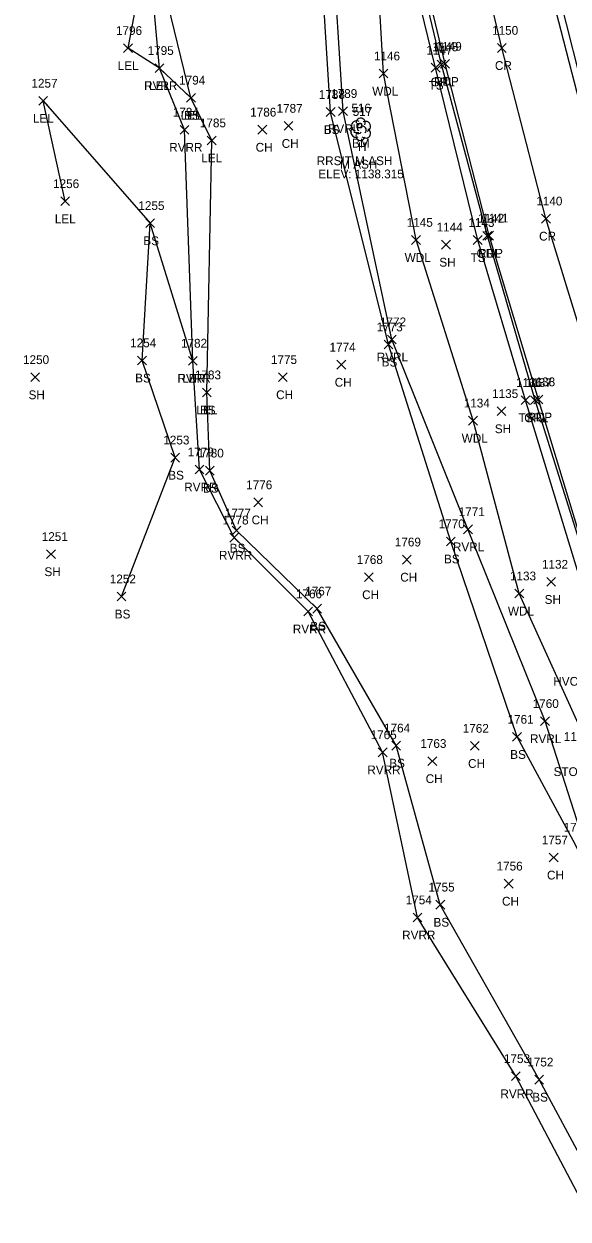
# Model space of a CAD drawing. Extents: x 1545627 to 1546562, y 571176 to 576667.
# Drawn here: x 1546048.6 to 1546172.5, y 571704.9 to 571977 of the extents above; entities that cross this region are included whole.
import ezdxf

# ---------------------------------------------------------------- set-up
doc = ezdxf.new("R2010")
doc.units = 0
for name, color, linetype in [('C_A', 7, 'Continuous'), ('C_C', 7, 'Continuous'), ('C_I', 7, 'Continuous'), ('CPBM', 7, 'Continuous'), ('L_A', 7, 'Continuous'), ('L_C', 7, 'Continuous'), ('L_I', 7, 'Continuous'), ('L_TIC', 7, 'Continuous'), ('LARO', 7, 'Continuous'), ('LAWA', 7, 'Continuous'), ('LAWE', 7, 'Continuous'), ('LELB', 7, 'Continuous'), ('LTD', 7, 'Continuous'), ('P_A', 7, 'Continuous'), ('P_I', 7, 'Continuous'), ('P_TIC', 7, 'Continuous'), ('PET', 7, 'Continuous'), ('PRC', 7, 'Continuous'), ('PSU', 7, 'Continuous'), ('R_A', 7, 'Continuous'), ('R_I', 7, 'Continuous'), ('R_TIC', 7, 'Continuous'), ('RGR', 7, 'Continuous')]:
    doc.layers.add(name, color=color, linetype=linetype)

msp = doc.modelspace()

# ---------------------------------------------------------------- linework, layer by layer
at = {"layer": 'CPBM'}
for p, q in [((1546124.51, 571953.36), (1546124.51, 571954.36)), ((1546124.51, 571954.36), (1546125.51, 571954.36)), ((1546125.51, 571953.36), (1546124.51, 571953.36)), ((1546125.01, 571953.86), (1546125.01, 571953.86)), ((1546125.01, 571953.86), (1546125.01, 571953.86)), ((1546125.51, 571954.36), (1546125.51, 571953.36))]:
    msp.add_line(p, q, dxfattribs=at)
at = {"layer": 'L_TIC'}
for points in [[(1546071.29, 571970.5), (1546073.29, 571972.5)], [(1546073.29, 571970.5), (1546071.29, 571972.5)], [(1546078.44, 571965.95), (1546080.44, 571967.95)], [(1546080.44, 571965.95), (1546078.44, 571967.95)], [(1546078.44, 571965.95), (1546080.44, 571967.95)], [(1546080.44, 571965.95), (1546078.44, 571967.95)], [(1546129.49, 571964.71), (1546131.49, 571966.71)], [(1546131.49, 571964.71), (1546129.49, 571966.71)], [(1546141.36, 571966.05), (1546143.36, 571968.05)], [(1546143.36, 571966.05), (1546141.36, 571968.05)], [(1546085.62, 571959.2), (1546087.62, 571961.2)], [(1546087.62, 571959.2), (1546085.62, 571961.2)], [(1546085.62, 571959.2), (1546087.62, 571961.2)], [(1546087.62, 571959.2), (1546085.62, 571961.2)], [(1546051.97, 571958.51), (1546053.97, 571960.51)], [(1546053.97, 571958.51), (1546051.97, 571960.51)], [(1546117.44, 571955.95), (1546119.44, 571957.95)], [(1546119.44, 571955.95), (1546117.44, 571957.95)], [(1546120.26, 571956.17), (1546122.26, 571958.17)], [(1546122.26, 571956.17), (1546120.26, 571958.17)], [(1546084.16, 571951.92), (1546086.16, 571953.92)], [(1546086.16, 571951.92), (1546084.16, 571953.92)], [(1546101.87, 571951.93), (1546103.87, 571953.93)], [(1546103.87, 571951.93), (1546101.87, 571953.93)], [(1546107.82, 571952.8), (1546109.82, 571954.8)], [(1546109.82, 571952.8), (1546107.82, 571954.8)], [(1546090.35, 571949.48), (1546092.35, 571951.48)], [(1546092.35, 571949.48), (1546090.35, 571951.48)], [(1546056.96, 571935.64), (1546058.96, 571937.64)], [(1546058.96, 571935.64), (1546056.96, 571937.64)], [(1546076.34, 571930.65), (1546078.34, 571932.65)], [(1546078.34, 571930.65), (1546076.34, 571932.65)], [(1546136.89, 571926.83), (1546138.89, 571928.83)], [(1546138.89, 571926.83), (1546136.89, 571928.83)], [(1546150.94, 571926.81), (1546152.94, 571928.81)], [(1546152.94, 571926.81), (1546150.94, 571928.81)], [(1546143.72, 571925.76), (1546145.72, 571927.76)], [(1546145.72, 571925.76), (1546143.72, 571927.76)], [(1546130.62, 571903.03), (1546132.62, 571905.03)], [(1546132.62, 571903.03), (1546130.62, 571905.03)], [(1546131.38, 571904.18), (1546133.38, 571906.18)], [(1546133.38, 571904.18), (1546131.38, 571906.18)], [(1546074.47, 571899.4), (1546076.47, 571901.4)], [(1546076.47, 571899.4), (1546074.47, 571901.4)], [(1546086.04, 571899.32), (1546088.04, 571901.32)], [(1546088.04, 571899.32), (1546086.04, 571901.32)], [(1546086.04, 571899.32), (1546088.04, 571901.32)], [(1546088.04, 571899.32), (1546086.04, 571901.32)], [(1546119.88, 571898.43), (1546121.88, 571900.43)], [(1546121.88, 571898.43), (1546119.88, 571900.43)], [(1546050.14, 571895.58), (1546052.14, 571897.58)], [(1546052.14, 571895.58), (1546050.14, 571897.58)], [(1546106.53, 571895.59), (1546108.53, 571897.59)], [(1546108.53, 571895.59), (1546106.53, 571897.59)], [(1546089.22, 571892.11), (1546091.22, 571894.11)], [(1546091.22, 571892.11), (1546089.22, 571894.11)], [(1546089.22, 571892.11), (1546091.22, 571894.11)], [(1546091.22, 571892.11), (1546089.22, 571894.11)], [(1546161.84, 571890.38), (1546163.84, 571892.38)], [(1546163.84, 571890.38), (1546161.84, 571892.38)], [(1546149.88, 571885.7), (1546151.88, 571887.7)], [(1546151.88, 571885.7), (1546149.88, 571887.7)], [(1546156.35, 571887.85), (1546158.35, 571889.85)], [(1546158.35, 571887.85), (1546156.35, 571889.85)], [(1546082.01, 571877.28), (1546084.01, 571879.28)], [(1546084.01, 571877.28), (1546082.01, 571879.28)], [(1546087.58, 571874.57), (1546089.58, 571876.57)], [(1546089.58, 571874.57), (1546087.58, 571876.57)], [(1546089.93, 571874.32), (1546091.93, 571876.32)], [(1546091.93, 571874.32), (1546089.93, 571876.32)], [(1546100.95, 571867.09), (1546102.95, 571869.09)], [(1546102.95, 571867.09), (1546100.95, 571869.09)], [(1546095.49, 571859.06), (1546097.49, 571861.06)], [(1546097.49, 571859.06), (1546095.49, 571861.06)], [(1546096.02, 571860.67), (1546098.02, 571862.67)], [(1546098.02, 571860.67), (1546096.02, 571862.67)], [(1546148.73, 571860.96), (1546150.73, 571862.96)], [(1546150.73, 571860.96), (1546148.73, 571862.96)], [(1546144.83, 571858.21), (1546146.83, 571860.21)], [(1546146.83, 571858.21), (1546144.83, 571860.21)], [(1546053.75, 571855.31), (1546055.75, 571857.31)], [(1546055.75, 571855.31), (1546053.75, 571857.31)], [(1546134.81, 571854.06), (1546136.81, 571856.06)], [(1546136.81, 571854.06), (1546134.81, 571856.06)], [(1546126.13, 571850.07), (1546128.13, 571852.07)], [(1546128.13, 571850.07), (1546126.13, 571852.07)], [(1546167.7, 571848.99), (1546169.7, 571850.99)], [(1546169.7, 571848.99), (1546167.7, 571850.99)], [(1546069.82, 571845.66), (1546071.82, 571847.66)], [(1546071.82, 571845.66), (1546069.82, 571847.66)], [(1546160.42, 571846.33), (1546162.42, 571848.33)], [(1546162.42, 571846.33), (1546160.42, 571848.33)], [(1546112.32, 571842.26), (1546114.32, 571844.26)], [(1546114.32, 571842.26), (1546112.32, 571844.26)], [(1546114.39, 571842.89), (1546116.39, 571844.89)], [(1546116.39, 571842.89), (1546114.39, 571844.89)], [(1546166.29, 571817.28), (1546168.29, 571819.28)], [(1546168.29, 571817.28), (1546166.29, 571819.28)], [(1546159.91, 571813.7), (1546161.91, 571815.7)], [(1546161.91, 571813.7), (1546159.91, 571815.7)], [(1546129.29, 571810.19), (1546131.29, 571812.19)], [(1546131.29, 571810.19), (1546129.29, 571812.19)], [(1546132.35, 571811.72), (1546134.35, 571813.72)], [(1546134.35, 571811.72), (1546132.35, 571813.72)], [(1546150.27, 571811.65), (1546152.27, 571813.65)], [(1546152.27, 571811.65), (1546150.27, 571813.65)], [(1546140.61, 571808.19), (1546142.61, 571810.19)], [(1546142.61, 571808.19), (1546140.61, 571810.19)], [(1546168.24, 571786.24), (1546170.24, 571788.24)], [(1546170.24, 571786.24), (1546168.24, 571788.24)], [(1546157.99, 571780.29), (1546159.99, 571782.29)], [(1546159.99, 571780.29), (1546157.99, 571782.29)], [(1546142.43, 571775.5), (1546144.43, 571777.5)], [(1546144.43, 571775.5), (1546142.43, 571777.5)], [(1546137.23, 571772.59), (1546139.23, 571774.59)], [(1546139.23, 571772.59), (1546137.23, 571774.59)], [(1546159.61, 571736.45), (1546161.61, 571738.45)], [(1546161.61, 571736.45), (1546159.61, 571738.45)], [(1546164.93, 571735.68), (1546166.93, 571737.68)], [(1546166.93, 571735.68), (1546164.93, 571737.68)]]:
    msp.add_lwpolyline(points, dxfattribs=at)
at = {"layer": 'LARO'}
for points in [[(1546090.22, 571893.11), (1546091.35, 571950.48), (1546086.62, 571960.2), (1546079.44, 571966.95), (1546072.29, 571971.5), (1546074.85, 571984.99), (1546068.68, 572037.28), (1546072.51, 572073.37), (1546063.14, 572085.78)], [(1546057.96, 571936.64), (1546052.97, 571959.51)], [(1546052.97, 571959.51), (1546077.34, 571931.65)], [(1546087.04, 571900.32), (1546077.34, 571931.65)]]:
    msp.add_lwpolyline(points, dxfattribs=at)
at = {"layer": 'LAWA'}
msp.add_lwpolyline([(1546207.43, 571744.29), (1546192.22, 571778.13), (1546177.19, 571812.62), (1546161.42, 571847.33), (1546150.88, 571886.7), (1546137.89, 571927.83), (1546130.49, 571965.71), (1546128.09, 572007.86), (1546121.49, 572030.97), (1546115.77, 572071.63), (1546116.87, 572083.76)], dxfattribs=at)
at = {"layer": 'LAWE'}
for points in [[(1546291.68, 571509.09), (1546276, 571554.51), (1546265.8, 571586.47), (1546246.73, 571630.75), (1546234.82, 571659.95), (1546216.56, 571711.52), (1546198.01, 571746.58), (1546176.48, 571789.7), (1546167.29, 571818.28), (1546149.73, 571861.96), (1546132.38, 571905.18), (1546121.26, 571957.17), (1546118.8, 571996.68)], [(1546258.96, 571503.98), (1546247.25, 571543.2), (1546232.25, 571576.91), (1546212.48, 571618.99), (1546196.14, 571656.31), (1546182.65, 571695.75), (1546160.61, 571737.45), (1546138.23, 571773.59), (1546130.29, 571811.19), (1546113.32, 571843.26), (1546096.49, 571860.06), (1546088.58, 571875.57), (1546087.04, 571900.32), (1546085.16, 571952.92), (1546079.44, 571966.95), (1546077.79, 571985.49)]]:
    msp.add_lwpolyline(points, dxfattribs=at)
at = {"layer": 'LELB'}
for points in [[(1546316.39, 571519.99), (1546295.99, 571560.57), (1546277.23, 571599.95), (1546257.92, 571640.86), (1546240.42, 571680.68), (1546227.25, 571713.56), (1546212.6, 571746.96), (1546199.61, 571780.81), (1546186.37, 571815.41), (1546174.93, 571851.82), (1546162.84, 571891.38), (1546151.94, 571927.81), (1546142.36, 571967.05), (1546132.26, 572008.4), (1546126.74, 572032.68), (1546118.89, 572071.99), (1546116.87, 572083.76)], [(1546086.62, 571960.2), (1546080.58, 571984.87), (1546076.82, 572034.33), (1546074.32, 572074.31)], [(1546289.09, 571508.47), (1546272.41, 571554.88), (1546264.55, 571586.76), (1546244.35, 571627.87), (1546230.42, 571657.81), (1546213.76, 571710.05), (1546197.12, 571744.15), (1546174.21, 571790.13), (1546160.91, 571814.7), (1546145.83, 571859.21), (1546131.62, 571904.03), (1546118.44, 571956.95), (1546115.97, 571995.99), (1546108.78, 572035.92), (1546103.73, 572068.58)], [(1546070.82, 571846.66), (1546083.01, 571878.28), (1546075.47, 571900.4), (1546077.34, 571931.65)], [(1546264.48, 571501.32), (1546248.81, 571543.43), (1546237.8, 571575.68), (1546217.63, 571618.65), (1546201.94, 571655.46), (1546187.64, 571696.37), (1546165.93, 571736.68), (1546143.43, 571776.5), (1546133.35, 571812.72), (1546115.39, 571843.89), (1546097.02, 571861.67), (1546090.93, 571875.32), (1546090.22, 571893.11)]]:
    msp.add_lwpolyline(points, dxfattribs=at)
at = {"layer": 'LTD'}
msp.add_line((1546125.25, 571953.07), (1546125.25, 571953.07), dxfattribs=at)
msp.add_line((1546125.25, 571953.07), (1546125.25, 571953.07), dxfattribs=at)
msp.add_arc((1546125.3, 571954.51), 1.05, 335.5272, 180.9563, dxfattribs=at)
for centre, major_axis, ratio, start_param, end_param in [((1546124.17, 571952.36), (0.58, -1.04), 0.959034, 3.141593, 6.283185), ((1546124.46, 571953.74), (1.21, -0.51), 0.895232, 1.570796, 4.712389), ((1546125.05, 571953.53), (-0.208, -0.792), 0.645439, 3.141593, 6.283185), ((1546125.75, 571952.9), (-0.5, 0.667), 0.989748, 3.141593, 6.283185), ((1546126.25, 571952.24), (-1.09, 0.79), 0.841452, 1.570796, 4.712389), ((1546126.3, 571953.66), (-1.14, -0.48), 0.949671, 1.570796, 4.712389), ((1546125.25, 571951.57), (0.26, 1.06), 0.942809, 1.570796, 4.712389), ((1546124.8, 571952.32), (-0.625, -0.083), 0.423636, 0, 3.141593)]:
    msp.add_ellipse(centre, major_axis=major_axis, ratio=ratio, start_param=start_param, end_param=end_param, dxfattribs=at)
at = {"layer": 'P_TIC'}
for points in [[(1546156.43, 571970.54), (1546158.43, 571972.54)], [(1546158.43, 571970.54), (1546156.43, 571972.54)], [(1546143.5, 571966.92), (1546145.5, 571968.92)], [(1546145.5, 571966.92), (1546143.5, 571968.92)], [(1546166.5, 571931.69), (1546168.5, 571933.69)], [(1546168.5, 571931.69), (1546166.5, 571933.69)], [(1546153.55, 571927.81), (1546155.55, 571929.81)], [(1546155.55, 571927.81), (1546153.55, 571929.81)], [(1546164.76, 571890.53), (1546166.76, 571892.53)], [(1546166.76, 571890.53), (1546164.76, 571892.53)]]:
    msp.add_lwpolyline(points, dxfattribs=at)
at = {"layer": 'PET'}
for points in [[(1546536.21, 571181.01), (1546508.17, 571223.67), (1546475.69, 571271.66), (1546448.41, 571311.32), (1546419.18, 571354.19), (1546394.92, 571390.86), (1546367.78, 571434.2), (1546346.92, 571469.65), (1546328.81, 571502.75), (1546318.67, 571520.99), (1546297.7, 571561.78), (1546279.07, 571601.48), (1546260.13, 571643.3), (1546242.96, 571682.18), (1546229.29, 571714.28), (1546215.95, 571747.93), (1546202.6, 571782.08), (1546189.82, 571816.62), (1546177.58, 571852.76), (1546165.76, 571891.53), (1546154.55, 571928.81), (1546144.5, 571967.92), (1546134.66, 572009.13)], [(1546559.08, 571194.5), (1546529.75, 571240.45), (1546499.79, 571284.88), (1546470.8, 571327.72), (1546443.13, 571367.68), (1546417.68, 571406.9), (1546392.95, 571446.31), (1546370.2, 571483.99), (1546352.76, 571515), (1546343.41, 571532.43), (1546322.94, 571573.04), (1546306.85, 571607.13), (1546293.98, 571634.56), (1546271.4, 571685.96), (1546259.46, 571713.47), (1546245.43, 571748.53), (1546227.67, 571795.22), (1546213.04, 571834.88), (1546205.18, 571857.76), (1546192.7, 571896.53), (1546178.72, 571945.47), (1546165.66, 571996.1)]]:
    msp.add_lwpolyline(points, dxfattribs=at)
at = {"layer": 'PRC'}
msp.add_lwpolyline([(1546547.34, 571187.72), (1546518.74, 571231.86), (1546487.31, 571278.43), (1546459.33, 571318.89), (1546430.57, 571360.77), (1546405.96, 571398.26), (1546380.25, 571440.1), (1546358.53, 571476.99), (1546340.41, 571508.44), (1546330.22, 571526.95), (1546310.11, 571567.47), (1546291.29, 571606.95), (1546272.42, 571649.01), (1546255.63, 571687.66), (1546242.53, 571719.45), (1546229.29, 571753.1), (1546216.08, 571786.74), (1546203.35, 571821.01), (1546191.26, 571856.19), (1546178.74, 571896.13), (1546167.5, 571932.69), (1546157.43, 571971.54), (1546147.89, 572011.79)], dxfattribs=at)
at = {"layer": 'PSU'}
msp.add_lwpolyline([(1546344.91, 571533.75), (1546324.24, 571573.75), (1546307.57, 571607.61), (1546295.25, 571635.34), (1546272.39, 571686.56), (1546261.3, 571714.23), (1546246.81, 571749.3), (1546229.82, 571796.03), (1546214.93, 571836.38), (1546208.22, 571856.11), (1546194.62, 571896.65), (1546180.08, 571945.81), (1546167.4, 571995.97), (1546161.66, 572024.84), (1546155.58, 572044.54)], dxfattribs=at)
at = {"layer": 'R_TIC'}
for points in [[(1546142.68, 571966.8), (1546144.68, 571968.8)], [(1546144.68, 571966.8), (1546142.68, 571968.8)], [(1546153.15, 571927.78), (1546155.15, 571929.78)], [(1546155.15, 571927.78), (1546153.15, 571929.78)], [(1546164.01, 571890.35), (1546166.01, 571892.35)], [(1546166.01, 571890.35), (1546164.01, 571892.35)]]:
    msp.add_lwpolyline(points, dxfattribs=at)
at = {"layer": 'RGR'}
msp.add_lwpolyline([(1546318.09, 571520.89), (1546297.39, 571561.7), (1546278.61, 571601.26), (1546259.67, 571643.05), (1546242.43, 571682.09), (1546228.78, 571714.21), (1546215.19, 571747.99), (1546202.24, 571781.5), (1546189.29, 571816.51), (1546177.18, 571852.71), (1546165.01, 571891.35), (1546154.15, 571928.78), (1546143.68, 571967.8), (1546133.91, 572008.79), (1546128.63, 572033), (1546121.13, 572073.3), (1546118.95, 572085.97)], dxfattribs=at)

# ---------------------------------------------------------------- texts
at = {"layer": 'C_A'}
for s, p in [('BM', (1546123.33, 571948.86)), ('HVCTRL', (1546169.17, 571826.35))]:
    msp.add_text(s, height=2, dxfattribs=at).set_placement(p)
at = {"layer": 'C_C'}
for s, p in [('RRSIT M ASH', (1546115.27, 571944.86)), ('ELEV: 1138.315', (1546115.63, 571941.86))]:
    msp.add_text(s, height=2, dxfattribs=at).set_placement(p)
at = {"layer": 'C_I'}
msp.add_text('516', height=2, dxfattribs=at).set_placement((1546123.16, 571956.86))
at = {"layer": 'L_A'}
for s, p in [('LEL', (1546069.93, 571966.5)), ('RVRR', (1546075.95, 571961.95)), ('LEL', (1546077.08, 571961.95)), ('TS', (1546140.77, 571962.05)), ('WDL', (1546127.91, 571960.71)), ('LEL', (1546050.61, 571954.51)), ('LEL', (1546084.26, 571955.2)), ('BS', (1546085.06, 571955.2)), ('BS', (1546116.88, 571951.95)), ('RVRL', (1546117.83, 571952.17)), ('CH', (1546107.3, 571948.8)), ('H', (1546124.69, 571948.07)), ('RVRR', (1546081.67, 571947.92)), ('LEL', (1546088.98, 571945.48)), ('CH', (1546101.36, 571947.93)), ('LEL', (1546055.6, 571931.64)), ('BS', (1546075.78, 571926.65)), ('WDL', (1546135.31, 571922.83)), ('SH', (1546143.2, 571921.76)), ('TS', (1546150.35, 571922.81)), ('RVRL', (1546128.94, 571900.18)), ('BS', (1546130.06, 571899.03)), ('BS', (1546073.91, 571895.4)), ('RVRR', (1546083.56, 571895.32)), ('LER', (1546084.63, 571895.32)), ('CH', (1546119.37, 571894.43)), ('SH', (1546049.63, 571891.58)), ('CH', (1546106.02, 571891.59)), ('LEL', (1546087.85, 571888.11)), ('BS', (1546088.66, 571888.11)), ('TS', (1546161.25, 571886.38)), ('SH', (1546155.84, 571883.85)), ('WDL', (1546148.3, 571881.7)), ('BS', (1546081.45, 571873.28)), ('RVRR', (1546085.09, 571870.57)), ('BS', (1546089.37, 571870.32)), ('CH', (1546100.44, 571863.09)), ('BS', (1546095.46, 571856.67)), ('RVRL', (1546146.3, 571856.96)), ('RVRR', (1546093, 571855.06)), ('BS', (1546144.27, 571854.21)), ('SH', (1546053.24, 571851.31)), ('CH', (1546134.3, 571850.06)), ('CH', (1546125.62, 571846.07)), ('SH', (1546167.19, 571844.99)), ('WDL', (1546158.83, 571842.33)), ('BS', (1546069.26, 571841.66)), ('RVRR', (1546109.83, 571838.26)), ('BS', (1546113.83, 571838.89)), ('RVRL', (1546163.86, 571813.28)), ('BS', (1546159.35, 571809.7)), ('BS', (1546131.79, 571807.72)), ('CH', (1546149.75, 571807.65)), ('RVRR', (1546126.8, 571806.19)), ('CH', (1546140.09, 571804.19)), ('STONE', (1546169.23, 571805.79)), ('CH', (1546167.73, 571782.24)), ('CH', (1546157.48, 571776.29)), ('BS', (1546141.87, 571771.5)), ('RVRR', (1546134.74, 571768.59)), ('RVRR', (1546157.12, 571732.45)), ('BS', (1546164.37, 571731.68))]:
    msp.add_text(s, height=2, dxfattribs=at).set_placement(p)
at = {"layer": 'L_C'}
msp.add_text('M ASH', height=2, dxfattribs=at).set_placement((1546120.62, 571944.07))
at = {"layer": 'L_I'}
for s, p in [('1796', (1546069.54, 571974.5)), ('1795', (1546076.75, 571969.95)), ('1795', (1546076.75, 571969.95)), ('1147', (1546140.23, 571970.05)), ('1146', (1546128.31, 571968.71)), ('1257', (1546050.28, 571962.51)), ('1794', (1546083.93, 571963.2)), ('1794', (1546083.93, 571963.2)), ('1788', (1546115.75, 571959.95)), ('1789', (1546118.56, 571960.17)), ('1787', (1546106.12, 571956.8)), ('1784', (1546082.47, 571955.92)), ('1785', (1546088.65, 571953.48)), ('1786', (1546100.12, 571955.93)), ('517', (1546123.46, 571956.07)), ('1256', (1546055.21, 571939.64)), ('1255', (1546074.64, 571934.65)), ('1145', (1546135.77, 571930.83)), ('1144', (1546142.59, 571929.76)), ('1143', (1546149.81, 571930.81)), ('1772', (1546129.68, 571908.18)), ('1773', (1546128.92, 571907.03)), ('1254', (1546072.77, 571903.4)), ('1782', (1546084.35, 571903.32)), ('1782', (1546084.35, 571903.32)), ('1774', (1546118.19, 571902.43)), ('1250', (1546048.36, 571899.58)), ('1775', (1546104.84, 571899.59)), ('1783', (1546087.52, 571896.11)), ('1783', (1546087.52, 571896.11)), ('1136', (1546160.66, 571894.38)), ('1135', (1546155.22, 571891.85)), ('1134', (1546148.76, 571889.7)), ('1253', (1546080.32, 571881.28)), ('1779', (1546085.88, 571878.57)), ('1780', (1546088.15, 571878.32)), ('1776', (1546099.2, 571871.09)), ('1777', (1546094.33, 571864.67)), ('1771', (1546147.61, 571864.96)), ('1778', (1546093.8, 571863.06)), ('1770', (1546143.05, 571862.21)), ('1251', (1546052.62, 571859.31)), ('1769', (1546133.06, 571858.06)), ('1768', (1546124.39, 571854.07)), ('1132', (1546166.58, 571852.99)), ('1133', (1546159.29, 571850.33)), ('1252', (1546068.13, 571849.66)), ('1766', (1546110.53, 571846.26)), ('1767', (1546112.65, 571846.89)), ('1760', (1546164.47, 571821.28)), ('1761', (1546158.74, 571817.7)), ('1764', (1546130.61, 571815.72)), ('1762', (1546148.53, 571815.65)), ('1765', (1546127.55, 571814.19)), ('1763', (1546138.87, 571812.19)), ('1122', (1546171.57, 571813.79)), ('1758', (1546171.52, 571793.13)), ('1757', (1546166.55, 571790.24)), ('1756', (1546156.24, 571784.29)), ('1755', (1546140.74, 571779.5)), ('1754', (1546135.54, 571776.59)), ('1753', (1546157.92, 571740.45)), ('1752', (1546163.24, 571739.68))]:
    msp.add_text(s, height=2, dxfattribs=at).set_placement(p)
at = {"layer": 'P_A'}
for s, p in [('CR', (1546155.87, 571966.54)), ('RDP', (1546141.99, 571962.92)), ('CR', (1546165.93, 571927.69)), ('RDP', (1546152.04, 571923.81)), ('RDP', (1546163.25, 571886.53))]:
    msp.add_text(s, height=2, dxfattribs=at).set_placement(p)
at = {"layer": 'P_I'}
for s, p in [('1150', (1546155.22, 571974.54)), ('1149', (1546142.36, 571970.92)), ('1140', (1546165.29, 571935.69)), ('1141', (1546152.99, 571931.81)), ('1138', (1546163.64, 571894.53))]:
    msp.add_text(s, height=2, dxfattribs=at).set_placement(p)
at = {"layer": 'R_A'}
for p in [(1546141.23, 571962.8), (1546151.69, 571923.78), (1546162.55, 571886.35)]:
    msp.add_text('GRL', height=2, dxfattribs=at).set_placement(p)
at = {"layer": 'R_I'}
for s, p in [('1148', (1546141.56, 571970.8)), ('1142', (1546152.02, 571931.78)), ('1137', (1546162.88, 571894.35))]:
    msp.add_text(s, height=2, dxfattribs=at).set_placement(p)

doc.saveas('drawing.dxf')
